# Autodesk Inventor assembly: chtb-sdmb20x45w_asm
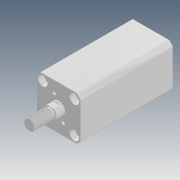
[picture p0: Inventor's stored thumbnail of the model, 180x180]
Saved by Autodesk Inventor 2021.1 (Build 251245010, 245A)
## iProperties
Company: Microsoft
Created: 2018-05
Part Number: chtb-sdmb20x45w_asm
Description: STEP AP214
Document SubType Name: Assembly
Designer: user
Title: chtb-sdmb20x45w_asm.STEP
Author: Windows
Revision Number: ÈÎºÎ
Sending System: SolidWorks 2015
Preprocessor: SwSTEP 2.0
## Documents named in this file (4)
- D:\Vault_2016\Projekty\Clamptek\Hydraulic\CHTB\CHTB-20\Inventor\CHTB-SDMB20x45W\chtb-sdmb20x45w_asm.iam
- D:\Vault_2016\Projekty\Clamptek\Hydraulic\CHTB\CHTB-20\Inventor\CHTB-SDMB20x45W\CHTB-SDMB20X45NBT.ipt
- D:\Vault_2016\Projekty\Clamptek\Hydraulic\CHTB\CHTB-20\Inventor\CHTB-SDMB20x45W\CHTB-SDMB20X45WHSG.ipt
- D:\Vault_2016\Projekty\Clamptek\Hydraulic\CHTB\CHTB-20\Inventor\CHTB-SDMB20x45W\QG_3.ipt
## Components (3 placed, 3 different names)
1. CHTB-SDMB20X45NBT_1
2. CHTB-SDMB20X45WHSG_2
3. QG_3_3
